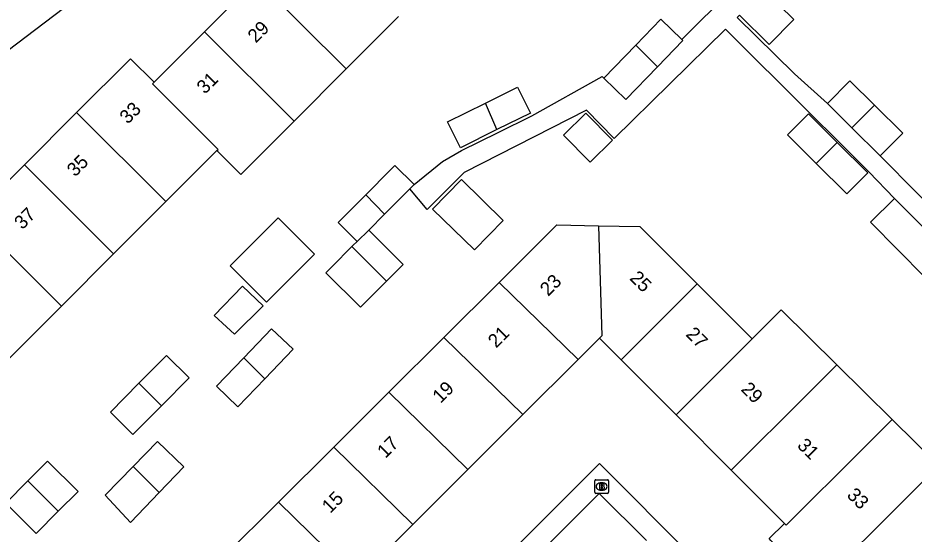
# Model space of a CAD drawing. Extents: x 159961 to 160856, y 382704 to 383353.
# Drawn here: x 160092.3 to 160157.8, y 383154.1 to 383191.9 of the extents above; entities that cross this region are included whole.
import ezdxf

# ---------------------------------------------------------------- set-up
doc = ezdxf.new("R2010")
doc.units = 0
for name, color, linetype in [('IMGEO_Brandkraan', 7, 'Continuous'), ('IMGEO_Pand', 7, 'Continuous'), ('IMGEO_Pand_nummerreeks', 7, 'Continuous'), ('IMGEO_Voetpad_open', 7, 'Continuous')]:
    doc.layers.add(name, color=color, linetype=linetype)

msp = doc.modelspace()

# ---------------------------------------------------------------- linework, layer by layer
at = {"layer": 'IMGEO_Brandkraan'}
for p, q in [((160134.451, 383157.148), (160134.451, 383158)), ((160134.526, 383158.074), (160135.378, 383158.074)), ((160134.939, 383157.854), (160134.964, 383157.854)), ((160135.452, 383158), (160135.452, 383157.148)), ((160134.962, 383157.294), (160134.937, 383157.294)), ((160135.378, 383157.074), (160134.526, 383157.074))]:
    msp.add_line(p, q, dxfattribs=at)
for points in [[(160134.451, 383157.148), (160134.451, 383158)], [(160134.526, 383158.074), (160135.378, 383158.074)], [(160135.452, 383158), (160135.452, 383157.148)], [(160134.799, 383157.774), (160134.799, 383157.374), (160135.012, 383157.374)], [(160135.03, 383157.774), (160134.799, 383157.774)], [(160134.978, 383157.693), (160134.924, 383157.693), (160134.924, 383157.617)], [(160134.924, 383157.617), (160134.977, 383157.617)], [(160134.986, 383157.541), (160134.924, 383157.541), (160134.924, 383157.46)], [(160134.924, 383157.46), (160134.986, 383157.46)], [(160135.378, 383157.074), (160134.526, 383157.074)]]:
    msp.add_lwpolyline(points, dxfattribs=at)
for centre, radius, start, end in [((160134.528, 383157.998), 0.0765, 91.55205, 178.44795), ((160134.528, 383157.998), 0.0765, 91.55205, 178.44795), ((160135.376, 383157.998), 0.0765, 1.55205, 88.44795), ((160135.376, 383157.998), 0.0765, 1.55205, 88.44795), ((160134.528, 383157.15), 0.0765, 181.55205, 268.44795), ((160134.528, 383157.15), 0.0765, 181.55205, 268.44795), ((160134.979, 383157.655), 0.0379, 267.82845, 90.93552), ((160134.987, 383157.5), 0.0404, 269.87594, 90.50774), ((160135.018, 383157.625), 0.251, 268.66757, 293.53466), ((160135.034, 383157.629), 0.145, 59.4692, 91.53667), ((160135.059, 383157.676), 0.0922, 285.51372, 58.15012), ((160135.064, 383157.484), 0.105, 301.31148, 78.98903), ((160135.376, 383157.15), 0.0765, 271.55205, 358.44795), ((160135.376, 383157.15), 0.0765, 271.55205, 358.44795)]:
    msp.add_arc(centre, radius, start, end, dxfattribs=at)
for centre, major_axis, ratio, start_param, end_param in [((160134.938, 383157.574), (-0.387, 0.002), 0.722429, 4.712389, 7.853982), ((160134.963, 383157.574), (-0.39, 0.002), 0.717154, 1.570796, 4.712389)]:
    msp.add_ellipse(centre, major_axis=major_axis, ratio=ratio, start_param=start_param, end_param=end_param, dxfattribs=at)
at = {"layer": 'IMGEO_Pand'}
for points in [[(160105.902, 383190.862), (160109.716, 383194.686)], [(160116.27, 383188.142), (160109.716, 383194.686)], [(160146.837, 383193.901), (160149.018, 383191.75), (160147.222, 383189.928), (160145.041, 383192.08)], [(160120.083, 383191.965), (160116.27, 383188.142)], [(160137.453, 383189.883), (160139.285, 383191.779), (160140.812, 383190.304)], [(160102.207, 383187.159), (160105.902, 383190.862)], [(160105.902, 383190.862), (160112.455, 383184.319)], [(160140.812, 383190.304), (160140.901, 383190.217), (160139.044, 383188.294)], [(160135.11, 383187.459), (160137.453, 383189.883)], [(160137.453, 383189.883), (160139.044, 383188.294)], [(160096.542, 383184.946), (160100.475, 383188.888), (160102.207, 383187.159)], [(160116.27, 383188.142), (160112.455, 383184.319)], [(160139.044, 383188.294), (160136.728, 383185.896), (160135.11, 383187.459)], [(160106.804, 383182.157), (160106.89, 383182.245), (160102.086, 383187.041), (160102.207, 383187.159)], [(160126.457, 383185.64), (160128.803, 383186.803), (160129.741, 383184.907), (160127.297, 383183.697)], [(160154.927, 383185.48), (160153.121, 383187.275), (160151.47, 383185.613)], [(160127.297, 383183.697), (160124.618, 383182.37), (160123.679, 383184.264), (160126.457, 383185.64)], [(160127.297, 383183.697), (160126.457, 383185.64)], [(160151.47, 383185.613), (160153.271, 383183.824)], [(160153.271, 383183.824), (160154.927, 383185.48)], [(160154.927, 383185.48), (160156.991, 383183.43), (160155.34, 383181.767)], [(160092.728, 383181.123), (160096.542, 383184.946)], [(160096.542, 383184.946), (160103.068, 383178.43)], [(160134.122, 383181.317), (160132.175, 383183.295), (160133.801, 383184.896), (160135.748, 383182.918), (160134.122, 383181.317)], [(160150.651, 383181.224), (160148.558, 383183.305), (160150.095, 383184.843), (160152.196, 383182.753)], [(160112.455, 383184.319), (160108.555, 383180.41), (160106.804, 383182.157)], [(160153.271, 383183.824), (160155.34, 383181.767)], [(160152.196, 383182.753), (160154.436, 383180.526), (160152.903, 383178.984), (160150.651, 383181.224)], [(160152.196, 383182.753), (160150.651, 383181.224)], [(160106.804, 383182.157), (160103.068, 383178.43)], [(160088.914, 383177.3), (160092.728, 383181.123)], [(160099.254, 383174.607), (160092.728, 383181.123)], [(160117.693, 383178.929), (160119.514, 383180.761), (160119.829, 383181.078), (160121.242, 383179.673)], [(160121.242, 383179.673), (160120.927, 383179.356)], [(160125.65, 383174.897), (160122.59, 383177.88), (160124.694, 383180.038), (160127.754, 383177.055), (160125.65, 383174.897)], [(160117.068, 383175.507), (160115.672, 383176.895), (160117.693, 383178.929)], [(160117.693, 383178.929), (160119.082, 383177.5)], [(160120.927, 383179.356), (160119.082, 383177.5)], [(160103.068, 383178.43), (160099.254, 383174.607)], [(160158.582, 383172.919), (160156.655, 383174.879), (160154.635, 383176.933), (160156.393, 383178.661)], [(160160.326, 383174.66), (160158.421, 383176.598), (160156.393, 383178.661)], [(160119.082, 383177.5), (160117.917, 383176.328)], [(160088.914, 383177.3), (160095.439, 383170.785)], [(160110.448, 383171.061), (160107.784, 383173.722), (160111.293, 383177.236), (160113.958, 383174.576), (160110.448, 383171.061)], [(160117.068, 383175.507), (160117.917, 383176.328)], [(160117.917, 383176.328), (160120.426, 383173.834), (160119.214, 383172.615)], [(160127.448, 383172.502), (160131.688, 383176.727), (160134.738, 383176.665)], [(160134.738, 383176.665), (160137.751, 383176.604), (160141.954, 383172.402)], [(160134.738, 383176.665), (160134.977, 383168.596), (160134.802, 383168.42)], [(160116.691, 383175.14), (160116.764, 383175.214), (160117.068, 383175.507)], [(160119.214, 383172.615), (160117.311, 383170.7), (160114.779, 383173.217), (160115.24, 383173.68), (160116.691, 383175.14)], [(160116.691, 383175.14), (160118.891, 383172.932), (160119.214, 383172.615)], [(160099.254, 383174.607), (160095.439, 383170.785)], [(160108.106, 383168.715), (160107.504, 383169.263), (160106.601, 383170.084), (160108.679, 383172.24), (160110.181, 383170.793), (160108.106, 383168.715)], [(160123.422, 383168.49), (160127.448, 383172.502)], [(160133.236, 383166.86), (160127.448, 383172.502)], [(160141.954, 383172.402), (160136.382, 383166.836)], [(160141.954, 383172.402), (160145.973, 383168.383)], [(160095.439, 383170.785), (160091.626, 383166.962)], [(160145.973, 383168.383), (160148.094, 383170.504), (160152.158, 383166.488)], [(160108.772, 383166.99), (160110.811, 383169.122), (160112.378, 383167.622), (160110.303, 383165.453)], [(160119.388, 383164.471), (160123.422, 383168.49)], [(160123.422, 383168.49), (160129.201, 383162.84)], [(160134.802, 383168.42), (160133.236, 383166.86)], [(160136.382, 383166.836), (160134.802, 383168.42)], [(160145.973, 383168.383), (160140.398, 383162.81)], [(160101.104, 383165.129), (160103.123, 383167.172), (160104.775, 383165.538), (160102.749, 383163.488)], [(160110.303, 383165.453), (160108.347, 383163.407), (160106.78, 383164.907), (160108.772, 383166.99)], [(160108.772, 383166.99), (160110.303, 383165.453)], [(160133.236, 383166.86), (160129.201, 383162.84)], [(160140.398, 383162.81), (160136.382, 383166.836)], [(160152.158, 383166.488), (160150.013, 383164.343), (160144.436, 383158.763)], [(160152.158, 383166.488), (160156.218, 383162.474)], [(160102.749, 383163.488), (160100.667, 383161.381), (160099.015, 383163.015), (160101.104, 383165.129)], [(160102.749, 383163.488), (160101.104, 383165.129)], [(160115.355, 383160.453), (160119.388, 383164.471)], [(160125.167, 383158.819), (160119.388, 383164.471)], [(160129.201, 383162.84), (160125.167, 383158.819)], [(160144.436, 383158.763), (160140.398, 383162.81)], [(160156.218, 383162.474), (160154.046, 383160.311), (160148.451, 383154.739), (160148.326, 383154.864)], [(160156.218, 383162.474), (160159.628, 383159.104)], [(160100.681, 383159.038), (160102.45, 383160.857), (160104.378, 383159.012), (160102.581, 383157.133)], [(160111.322, 383156.434), (160115.355, 383160.453)], [(160115.355, 383160.453), (160121.131, 383154.799)], [(160092.979, 383157.981), (160094.421, 383159.426), (160096.648, 383157.205), (160095.205, 383155.759)], [(160159.628, 383159.104), (160157.436, 383156.92), (160150.732, 383150.239)], [(160102.581, 383157.133), (160100.492, 383154.949), (160098.641, 383156.94), (160100.681, 383159.038)], [(160100.681, 383159.038), (160102.311, 383157.404), (160102.581, 383157.133)], [(160125.167, 383158.819), (160121.131, 383154.799)], [(160148.326, 383154.864), (160144.436, 383158.763)], [(160095.205, 383155.759), (160093.575, 383154.125), (160091.378, 383156.358), (160092.979, 383157.981)], [(160095.205, 383155.759), (160092.979, 383157.981)], [(160107.289, 383152.415), (160111.322, 383156.434)], [(160111.322, 383156.434), (160117.096, 383150.778)], [(160121.131, 383154.799), (160117.096, 383150.778)], [(160150.732, 383150.239), (160147.341, 383153.633), (160147.202, 383153.773), (160148.326, 383154.864)]]:
    msp.add_lwpolyline(points, dxfattribs=at)
at = {"layer": 'IMGEO_Voetpad_open'}
for points in [[(160043.886, 383151.186), (160054.318, 383161.568), (160054.98, 383162.099), (160069.776, 383173.027), (160139.659, 383226.049), (160145.341, 383230.36)], [(160140.812, 383190.304), (160144.423, 383193.903)], [(160145.041, 383192.08), (160144.872, 383191.909), (160149.065, 383187.772), (160151.47, 383185.613)], [(160156.393, 383178.661), (160154.514, 383180.604), (160152.274, 383182.831), (160150.173, 383184.921), (160144.01, 383191.052), (160135.884, 383183.052), (160133.851, 383185.116), (160124.902, 383180.566), (160122.19, 383177.859), (160120.927, 383179.356)], [(160121.242, 383179.673), (160123.31, 383181.366), (160124.715, 383182.174), (160127.384, 383183.496), (160129.838, 383184.712), (160134.993, 383187.572), (160135.11, 383187.459)], [(160155.34, 383181.767), (160155.814, 383181.296), (160159.296, 383177.772)], [(160088.71, 383106.25), (160113.509, 383131.154), (160110.154, 383134.627), (160134.789, 383159.249), (160175.896, 383118.003), (160179.441, 383121.518), (160198.785, 383102.122)], [(160115.778, 383131.258), (160112.417, 383134.711), (160134.765, 383157.073), (160138.232, 383153.621)]]:
    msp.add_lwpolyline(points, dxfattribs=at)

# ---------------------------------------------------------------- texts
at = {"layer": 'IMGEO_Pand_nummerreeks'}
for s, rotation, p in [('29', 45.06571, (160109.661, 383189.985)), ('31', 45.06571, (160105.931, 383186.246)), ('33', 45.06561, (160100.288, 383184.055)), ('35', 45.06561, (160096.435, 383180.193)), ('37', 45.06561, (160092.582, 383176.332)), ('23', 44.89728, (160131.043, 383171.453)), ('25', 315.00348, (160136.951, 383172.766)), ('21', 44.89728, (160127.236, 383167.661)), ('27', 315.00348, (160141.062, 383168.655)), ('19', 44.89728, (160123.177, 383163.617)), ('29', 314.99989, (160145.089, 383164.629)), ('17', 44.89728, (160119.134, 383159.589)), ('31', 315.00562, (160149.206, 383160.512)), ('15', 44.89728, (160115.091, 383155.56)), ('33', 314.99417, (160152.839, 383156.879))]:
    msp.add_text(s, height=1, rotation=rotation, dxfattribs=at).set_placement(p)

doc.saveas('drawing.dxf')
